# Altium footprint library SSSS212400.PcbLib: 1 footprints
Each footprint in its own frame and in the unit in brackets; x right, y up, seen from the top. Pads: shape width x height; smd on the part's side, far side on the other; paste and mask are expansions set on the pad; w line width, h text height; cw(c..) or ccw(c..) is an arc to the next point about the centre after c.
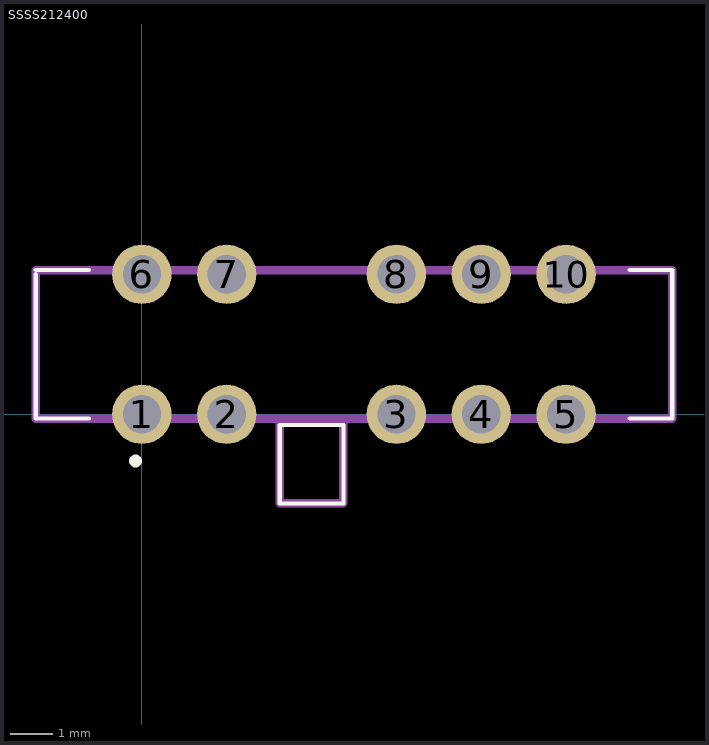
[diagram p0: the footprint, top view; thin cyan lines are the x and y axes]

## SSSS212400 [mm]
pads (10):
  round 1.4 hole 0.9: 1(0,0) 2(2,0) 3(6,0) 4(8,0) 5(10,0) 6(0,3.3) 7(2,3.3) 8(6,3.3) 9(8,3.3) 10(10,3.3)
Top Overlay:
  lines w0.1: -2.5,-0.1 -2.5,3.3 -2.5,-0.1 ; -2.5,-0.1 -1.25,-0.1 -2.5,-0.1 ; 12.5,-0.1 12.5,3.4 ; 12.5,-0.1 12.5,3.4 ; 12.5,-0.1 11.5,-0.1 12.5,-0.1 ; 12.5,3.4 11.5,3.4 12.5,3.4 ; -2.5,3.4 -1.25,3.4 -2.5,3.4 ; 3.25,-2.1 3.25,-0.25 4.75,-0.25 4.75,-2.1 3.25,-2.1
  lines w0.2: -0.2,-1.1 ccw(c-0.15,-1.1) -0.1,-1.1 ; -0.2,-1.1 cw(c-0.15,-1.1) -0.1,-1.1 ; -0.2,-1.1 ccw(c-0.15,-1.1) -0.1,-1.1
Mechanical 13:
  lines w0.2: -2.5,-0.1 -2.5,3.4 12.5,3.4 12.5,-0.1 -2.5,-0.1 ; 3.25,-2.1 3.25,-0.1 4.75,-0.1 4.75,-2.1 3.25,-2.1
3D body "SSSS212400.stp": height 3.6, standoff -5, extent -2.5,-2.1 12.5,3.649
